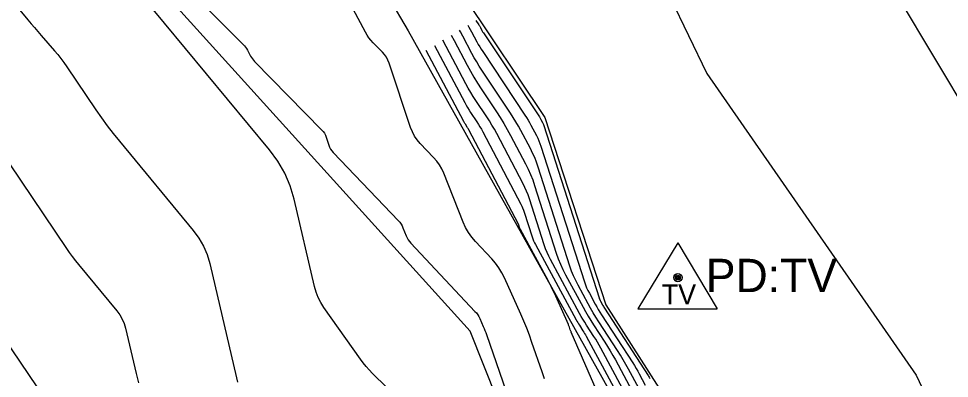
# Model space of a CAD drawing. Extents: x 1574966 to 1597594, y 720505 to 737840.
# Drawn here: x 1578007.3 to 1578146.9, y 724174.6 to 724228.5 of the extents above; entities that cross this region are included whole.
import ezdxf

# ---------------------------------------------------------------- set-up
doc = ezdxf.new("R2010")
doc.units = 0
for name, color, linetype in [('Default', 7, 'Continuous'), ('R_Contours', 7, 'Continuous'), ('S_BREAKLINE', 7, 'Continuous'), ('S_SECONDARY_CTL', 7, 'Continuous'), ('S_SECONDARY_CTL_ANNOT', 7, 'Continuous'), ('S_STREAM', 7, 'Continuous')]:
    doc.layers.add(name, color=color, linetype=linetype)

msp = doc.modelspace()

# ---------------------------------------------------------------- linework, layer by layer
at = {"layer": 'Default'}
msp.add_lwpolyline([(1578106.22, 724189.72), (1578106.22, 724189.77), (1578106.22, 724189.72), (1578106.17, 724189.72), (1578106.22, 724189.72), (1578106.22, 724189.67), (1578106.22, 724189.72), (1578106.27, 724189.72)], dxfattribs=at)
msp.add_lwpolyline([(1578106.22, 724189.72), (1578106.22, 724189.77), (1578106.22, 724189.72), (1578106.17, 724189.72), (1578106.22, 724189.72), (1578106.22, 724189.67), (1578106.22, 724189.72), (1578106.27, 724189.72)], dxfattribs=at)
msp.add_lwpolyline([(1578106.22, 724189.72), (1578106.22, 724189.77), (1578106.22, 724189.72), (1578106.17, 724189.72), (1578106.22, 724189.72), (1578106.22, 724189.67), (1578106.22, 724189.72), (1578106.27, 724189.72)], dxfattribs=at)
at = {"layer": 'R_Contours'}
for points in [[(1577993.05, 724247.2), (1578008.71, 724228.35), (1578009.2, 724227.77), (1578009.69, 724227.19), (1578010.19, 724226.61), (1578010.69, 724226.03), (1578012.7, 724223.73), (1578013.19, 724223.15), (1578013.67, 724222.55), (1578014.12, 724221.94), (1578014.56, 724221.31), (1578018.92, 724214.87), (1578019.75, 724213.66), (1578020.62, 724212.47), (1578021.51, 724211.31), (1578022.44, 724210.16), (1578033.52, 724196.76), (1578034.36, 724195.62), (1578035.05, 724194.41), (1578035.59, 724193.13), (1578035.99, 724191.78), (1578040.01, 724174.62), (1578040.17, 724174)], [(1578030.36, 724235.39), (1578041.05, 724224.62), (1578041.22, 724224.44), (1578041.37, 724224.24), (1578041.52, 724224.04), (1578041.64, 724223.82), (1578042.12, 724222.92), (1578042.25, 724222.7), (1578042.39, 724222.5), (1578042.54, 724222.3), (1578042.72, 724222.11), (1578052.78, 724211.82), (1578052.99, 724211.58), (1578053.17, 724211.33), (1578053.32, 724211.05), (1578053.43, 724210.75), (1578053.84, 724209.53), (1578053.96, 724209.23), (1578054.1, 724208.95), (1578054.28, 724208.69), (1578054.49, 724208.45), (1578064.27, 724198.22), (1578064.48, 724197.98), (1578064.66, 724197.72), (1578064.82, 724197.44), (1578064.95, 724197.15), (1578065.43, 724195.94), (1578065.57, 724195.65), (1578065.72, 724195.37), (1578065.91, 724195.11), (1578066.12, 724194.87), (1578075.75, 724184.61), (1578075.97, 724184.37), (1578076.16, 724184.11), (1578076.32, 724183.83), (1578076.47, 724183.54), (1578077, 724182.35), (1578077.13, 724182.05), (1578077.25, 724181.75), (1578077.37, 724181.45), (1578077.48, 724181.14), (1578082.81, 724165.65)], [(1578086.17, 724174.51), (1578085.81, 724175.52), (1578084.29, 724179.95), (1578083.91, 724181.02), (1578083.5, 724182.09), (1578083.07, 724183.14), (1578082.62, 724184.18), (1578080.18, 724189.62), (1578079.79, 724190.4), (1578079.34, 724191.14), (1578078.83, 724191.85), (1578078.26, 724192.51), (1578075.84, 724195.08), (1578075.27, 724195.74), (1578074.77, 724196.45), (1578074.34, 724197.2), (1578073.98, 724198), (1578071.06, 724205.34), (1578070.77, 724205.99), (1578070.42, 724206.6), (1578070.01, 724207.17), (1578069.54, 724207.71), (1578067.55, 724209.79), (1578067.09, 724210.33), (1578066.69, 724210.91), (1578066.36, 724211.54), (1578066.1, 724212.2), (1578062.88, 724221.88), (1578062.7, 724222.33), (1578062.47, 724222.76), (1578062.2, 724223.15), (1578061.88, 724223.52), (1578060.49, 724224.93), (1578060.16, 724225.3), (1578059.86, 724225.68), (1578059.58, 724226.08), (1578059.34, 724226.51), (1578054.87, 724234.86)], [(1578064.65, 724171.14), (1578060.4, 724175.31), (1578059.91, 724175.82), (1578059.44, 724176.34), (1578059, 724176.89), (1578058.58, 724177.46), (1578053.11, 724185.2), (1578052.64, 724185.93), (1578052.25, 724186.69), (1578051.94, 724187.49), (1578051.7, 724188.32), (1578048.63, 724201.47), (1578048.04, 724203.47), (1578047.23, 724205.37), (1578046.21, 724207.16), (1578044.97, 724208.85), (1578026.04, 724231.73)], [(1578074.68, 724227.54), (1578074.84, 724227.28), (1578075.05, 724226.92), (1578075.25, 724226.54), (1578076.04, 724225.05), (1578076.25, 724224.68), (1578076.46, 724224.31), (1578076.68, 724223.95), (1578076.91, 724223.6), (1578083.24, 724214.08), (1578083.48, 724213.71), (1578083.71, 724213.33), (1578083.93, 724212.95), (1578084.14, 724212.57), (1578084.96, 724211.01), (1578085.15, 724210.62), (1578085.33, 724210.22), (1578085.49, 724209.81), (1578085.64, 724209.39), (1578092.17, 724189.04), (1578092.32, 724188.6), (1578092.49, 724188.16), (1578092.68, 724187.74), (1578092.9, 724187.33), (1578093.78, 724185.69), (1578094.01, 724185.28), (1578094.24, 724184.87), (1578094.48, 724184.48), (1578094.73, 724184.08), (1578099.41, 724176.87), (1578099.66, 724176.47), (1578099.91, 724176.06), (1578100.15, 724175.65), (1578100.37, 724175.23), (1578101.27, 724173.56)], [(1578075.88, 724228.27), (1578076.34, 724227.59), (1578076.4, 724227.49), (1578076.46, 724227.39), (1578076.52, 724227.29), (1578076.57, 724227.19), (1578076.79, 724226.78), (1578076.84, 724226.68), (1578076.9, 724226.58), (1578076.96, 724226.48), (1578077.02, 724226.39), (1578085.4, 724213.8), (1578085.47, 724213.7), (1578085.53, 724213.6), (1578085.59, 724213.49), (1578085.64, 724213.39), (1578085.87, 724212.97), (1578085.92, 724212.86), (1578085.97, 724212.75), (1578086.01, 724212.64), (1578086.05, 724212.53), (1578094.35, 724186.66), (1578094.39, 724186.53), (1578094.45, 724186.39), (1578094.51, 724186.26), (1578094.58, 724186.13), (1578094.86, 724185.61), (1578094.93, 724185.48), (1578095, 724185.35), (1578095.08, 724185.23), (1578095.16, 724185.1), (1578101.71, 724174.99), (1578101.78, 724174.87), (1578101.85, 724174.76), (1578101.92, 724174.64), (1578101.99, 724174.52)], [(1578072.18, 724226.04), (1578072.61, 724225.25), (1578074.56, 724221.57), (1578075.06, 724220.66), (1578075.58, 724219.77), (1578076.12, 724218.88), (1578076.68, 724218.01), (1578078.98, 724214.56), (1578079.54, 724213.69), (1578080.08, 724212.81), (1578080.6, 724211.91), (1578081.09, 724211), (1578083.32, 724206.77), (1578083.72, 724205.97), (1578084.08, 724205.16), (1578084.4, 724204.33), (1578084.69, 724203.48), (1578087.94, 724193.35), (1578088.23, 724192.52), (1578088.56, 724191.7), (1578088.92, 724190.91), (1578089.32, 724190.12), (1578091.95, 724185.26), (1578092.33, 724184.58), (1578092.72, 724183.91), (1578093.12, 724183.25), (1578093.53, 724182.59), (1578095.22, 724179.99), (1578095.64, 724179.34), (1578096.04, 724178.67), (1578096.42, 724178), (1578096.8, 724177.32), (1578099.72, 724171.89)], [(1578100.3, 724173.09), (1578098.76, 724175.95), (1578098.37, 724176.66), (1578097.97, 724177.36), (1578097.55, 724178.06), (1578097.11, 724178.74), (1578094.31, 724183.06), (1578093.89, 724183.72), (1578093.49, 724184.4), (1578093.09, 724185.08), (1578092.71, 724185.76), (1578091.22, 724188.53), (1578090.86, 724189.23), (1578090.53, 724189.94), (1578090.24, 724190.67), (1578089.99, 724191.41), (1578085.22, 724206.26), (1578084.98, 724206.98), (1578084.7, 724207.68), (1578084.39, 724208.37), (1578084.05, 724209.05), (1578082.64, 724211.75), (1578082.27, 724212.41), (1578081.9, 724213.07), (1578081.5, 724213.72), (1578081.09, 724214.36), (1578076.8, 724220.8), (1578076.4, 724221.42), (1578076.02, 724222.04), (1578075.65, 724222.67), (1578075.3, 724223.31), (1578073.93, 724225.9), (1578073.58, 724226.54), (1578073.43, 724226.8)], [(1578069.67, 724224.53), (1578074.23, 724215.94), (1578074.43, 724215.56), (1578074.65, 724215.19), (1578074.87, 724214.83), (1578075.1, 724214.47), (1578076.05, 724213.04), (1578076.28, 724212.68), (1578076.5, 724212.32), (1578076.72, 724211.95), (1578076.92, 724211.57), (1578082.63, 724200.72), (1578082.77, 724200.42), (1578082.9, 724200.13), (1578083.02, 724199.82), (1578083.13, 724199.52), (1578084.32, 724195.81), (1578084.42, 724195.51), (1578084.54, 724195.21), (1578084.67, 724194.92), (1578084.82, 724194.63), (1578090.93, 724183.35), (1578091.04, 724183.14), (1578091.16, 724182.93), (1578091.29, 724182.72), (1578091.42, 724182.52), (1578091.94, 724181.71), (1578092.07, 724181.51), (1578092.19, 724181.3), (1578092.31, 724181.1), (1578092.43, 724180.89), (1578098.95, 724168.75)], [(1578099.34, 724170.32), (1578094.61, 724179.1), (1578094.37, 724179.55), (1578094.11, 724179.99), (1578093.85, 724180.42), (1578093.58, 724180.85), (1578092.48, 724182.56), (1578092.2, 724182.98), (1578091.94, 724183.42), (1578091.69, 724183.86), (1578091.44, 724184.3), (1578087.07, 724192.38), (1578086.8, 724192.91), (1578086.55, 724193.46), (1578086.33, 724194.01), (1578086.13, 724194.58), (1578083.91, 724201.5), (1578083.71, 724202.08), (1578083.49, 724202.64), (1578083.24, 724203.2), (1578082.97, 724203.74), (1578079.01, 724211.29), (1578078.66, 724211.93), (1578078.29, 724212.57), (1578077.91, 724213.19), (1578077.51, 724213.8), (1578075.89, 724216.24), (1578075.49, 724216.85), (1578075.11, 724217.48), (1578074.75, 724218.11), (1578074.39, 724218.75), (1578070.93, 724225.29)], [(1578096.13, 724167.83), (1578090.19, 724181.47), (1578090.15, 724181.57), (1578090.11, 724181.66), (1578090.07, 724181.76), (1578090.04, 724181.86), (1578089.9, 724182.25), (1578089.87, 724182.35), (1578089.83, 724182.45), (1578089.79, 724182.55), (1578089.75, 724182.64), (1578087.85, 724186.88), (1578087.51, 724187.61), (1578087.16, 724188.34), (1578086.8, 724189.06), (1578086.42, 724189.77), (1578082.57, 724196.89), (1578082.55, 724196.92), (1578082.53, 724196.96), (1578082.52, 724197), (1578082.5, 724197.04), (1578082.35, 724197.53), (1578082.33, 724197.57), (1578082.32, 724197.61), (1578082.3, 724197.65), (1578082.28, 724197.69), (1578074.84, 724211.86), (1578074.78, 724211.97), (1578074.72, 724212.07), (1578074.65, 724212.18), (1578074.58, 724212.28), (1578074.31, 724212.69), (1578074.24, 724212.8), (1578074.18, 724212.9), (1578074.12, 724213.01), (1578074.06, 724213.12), (1578068.41, 724223.77)], [(1578004.17, 724209.34), (1578014.5, 724194.07), (1578014.93, 724193.44), (1578015.38, 724192.83), (1578015.85, 724192.22), (1578016.32, 724191.63), (1578022.08, 724184.67), (1578022.51, 724184.08), (1578022.87, 724183.45), (1578023.15, 724182.79), (1578023.36, 724182.08), (1578024.96, 724175.27), (1578025.31, 724173.91)], [(1577993.79, 724197.37), (1578010.08, 724173.27)]]:
    msp.add_lwpolyline(points, dxfattribs=at)
at = {"layer": 'S_BREAKLINE'}
for p, q in [((1578075.05, 724181.63), (1577881.29, 724395.93)), ((1578079.63, 724284.39), (1578110.5, 724220.3)), ((1578137.65, 724234.36), (1578164.85, 724188.72)), ((1578110.5, 724220.3), (1578141.87, 724175.04)), ((1578132.36, 724038.09), (1578075.05, 724181.63)), ((1578141.87, 724175.04), (1578155.58, 724146.25))]:
    msp.add_line(p, q, dxfattribs=at)
at = {"layer": 'S_SECONDARY_CTL'}
for p, q in [((1578106.17, 724194.9), (1578100.15, 724184.99)), ((1578106.17, 724194.9), (1578100.15, 724184.99)), ((1578106.17, 724194.9), (1578100.15, 724184.99)), ((1578106.18, 724194.89), (1578100.16, 724184.98)), ((1578106.18, 724194.89), (1578100.16, 724184.98)), ((1578106.18, 724194.89), (1578100.16, 724184.98)), ((1578106.17, 724194.9), (1578112.07, 724184.99)), ((1578106.17, 724194.9), (1578112.07, 724184.99)), ((1578106.17, 724194.9), (1578112.07, 724184.99)), ((1578106.18, 724194.89), (1578112.08, 724184.98)), ((1578106.18, 724194.89), (1578112.08, 724184.98)), ((1578106.18, 724194.89), (1578112.08, 724184.98)), ((1578100.15, 724184.99), (1578112.07, 724184.99)), ((1578100.15, 724184.99), (1578112.07, 724184.99)), ((1578100.15, 724184.99), (1578112.07, 724184.99)), ((1578100.16, 724184.98), (1578112.08, 724184.98)), ((1578100.16, 724184.98), (1578112.08, 724184.98)), ((1578100.16, 724184.98), (1578112.08, 724184.98))]:
    msp.add_line(p, q, dxfattribs=at)
for centre, radius in [((1578106.17, 724189.68), 0.622), ((1578106.17, 724189.68), 0.622), ((1578106.17, 724189.68), 0.622), ((1578106.18, 724189.67), 0.622), ((1578106.18, 724189.67), 0.622), ((1578106.18, 724189.67), 0.622), ((1578106.17, 724189.68), 0.365), ((1578106.17, 724189.68), 0.365), ((1578106.17, 724189.68), 0.365), ((1578106.18, 724189.67), 0.365), ((1578106.18, 724189.67), 0.365), ((1578106.18, 724189.67), 0.365), ((1578106.17, 724189.68), 0.207), ((1578106.17, 724189.68), 0.207), ((1578106.17, 724189.68), 0.207), ((1578106.18, 724189.67), 0.207), ((1578106.18, 724189.67), 0.207), ((1578106.18, 724189.67), 0.207)]:
    msp.add_circle(centre, radius, dxfattribs=at)
at = {"layer": 'S_STREAM'}
for p, q in [((1578035.26, 724277.97), (1578065.75, 724226.72)), ((1578067.92, 724241.17), (1578086.2, 724213.69)), ((1578065.75, 724226.72), (1578098.7, 724167.74)), ((1578086.2, 724213.69), (1578095.35, 724185.57)), ((1578095.35, 724185.57), (1578109.92, 724162.89))]:
    msp.add_line(p, q, dxfattribs=at)

# ---------------------------------------------------------------- texts
at = {"layer": 'S_SECONDARY_CTL'}
for p in [(1578103.76, 724185.65), (1578103.76, 724185.65), (1578103.76, 724185.65), (1578103.77, 724185.65), (1578103.77, 724185.65), (1578103.77, 724185.65)]:
    msp.add_text('TV', height=3, rotation=360, dxfattribs=at).set_placement(p)
at = {"layer": 'S_SECONDARY_CTL_ANNOT'}
msp.add_text('PD:TV', height=5, dxfattribs=at).set_placement((1578110.35, 724187.5))

doc.saveas('drawing.dxf')
